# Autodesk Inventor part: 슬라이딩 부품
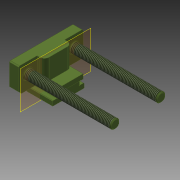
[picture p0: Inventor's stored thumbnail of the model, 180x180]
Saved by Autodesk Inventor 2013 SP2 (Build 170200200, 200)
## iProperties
Created: 2017-04
Part Number: 슬라이딩 부품
Material: 강철, 연강
Document SubType Name: Modeling
Designer: mduedu
Density: 1 g/cm^3
Author: mduedu
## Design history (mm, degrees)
sketch "스케치1"
  geometry: L1 (37, 35)-(10, 35); L2 (0, 17)-(0, 0); L3 (0, 17)-(5, 17); L4 (5, 17)-(5, 12); L5 (5, 12)-(10, 12); L6 (10, 12)-(10, 35); L7 (37, 35)-(37, 0); L8 (37, 0)-(0, 0); L9 (37, -35)-(10, -35); L10 (0, -17)-(0, 0); L11 (0, -17)-(5, -17); L12 (5, -17)-(5, -12); L13 (5, -12)-(10, -12); L14 (10, -12)-(10, -35); L15 (37, -35)-(37, 0)
  constraints: 30 end point, 6 symmetric about line, 3 perpendicular, 2 horizontal, 2 point on line, 2 vertical
  dimensions: "d39" = 5 distance of L2.start L3.end; "d41" = 70 distance between parallel lines of L9 L1; "d42" = 27 distance of L9.start L9.end; "d43" = 24 distance between parallel lines of L13 L5; "d44" = 5 distance of L4.end L5.end; "d45" = 34 distance between parallel lines of L11 L3
extrude "돌출1" new body sketch "스케치1" distance "d5" = 10; taper "d6" = 0 deg
sketch "스케치2"
  geometry: L1 (-35, 10)-(-35, 37) reference; L2 (17, 0)-(-17, 0) reference; L3 (-17, 0)-(-17, 5) reference; L4 (-17, 5)-(-12, 5) reference; L5 (-12, 5)-(-12, 10) reference; L6 (-12, 10)-(-35, 10) reference; L7 (-35, 37)-(35, 37) reference; L8 (35, 37)-(35, 10) reference; L9 (35, 10)-(12, 10) reference; L10 (12, 10)-(12, 5) reference; L11 (12, 5)-(17, 5) reference; L12 (17, 5)-(17, 0) reference; L13 (-12, 10)-(-15, 10); L14 (-15, 10)-(-15, 15); L15 (-15, 15)-(15, 15); L16 (15, 15)-(15, 10); L17 (15, 10)-(12, 10)
  constraints: 10 end point, 4 perpendicular, 2 point on line
  dimensions: "d46" = 3 distance between parallel lines of L14 L5; "d47" = 3 distance between parallel lines of L16 L10 (= d46); "d48" = 5 distance of L13.end L14.end
extrude "돌출2" join sketch "스케치2" distance "d12" = 20; taper "d13" = 0 deg
sketch "스케치3"
  geometry: L1 (0, 20)-(8, 20); L2 (8, 20)-(8, 50); L3 (8, 50)-(0, 50); L4 (0, 50)-(0, 20); L5 (0, 50)-(20, 50) reference; L6 (0, 20)-(20, 20) reference; L7 (0, 0)-(0, 70) reference; 2 further points
  constraints: 8 end point, 2 midpoint, 2 parallel, 1 horizontal, 1 perpendicular, 1 point on line
  dimensions: "d14" = 8 distance between parallel lines of L2 L4
extrude "돌출3" join sketch "스케치3" stored distance "d16" = 20; taper "d17" = 0 deg
fillet "모깎기1" dims "d18" = 5
sketch "스케치4"
  geometry: L1 (-15, 10)-(-35, 10) reference; L2 (-35, 10)-(-35, 37) reference; C1 r 5 at (-25, 25); 1 further point
  constraints: 1 centre point
  dimensions: "d19" = 10 diameter of C1; "d23" = 25 horizontal distance of point (0, 0) C1.centre (derived); "d49" = 15 distance from line of C1.centre L1; "d50" = 10 distance from line of C1.centre L2
extrude "돌출4" join sketch "스케치4" distance "d24" = 95; taper "d25" = 0 deg
feature "스레드1" dims "d26" = 10, "d27" = 0
chamfer "모따기1" distance "d28" = 1; stored, may be unused: second distance "d29" = 2, angle "d30" = 45 deg
fillet "모깎기2" dims "d31" = 1
sketch "스케치5"
  geometry: L1 (-12, 5)-(-12, 10) reference; L2 (12, 10)-(12, 5) reference; C1 r 0.5 at (-12, 10); C2 r 0.5 at (-12, 5); C3 r 0.5 at (12, 5); C4 r 0.5 at (12, 10); 1 further point
  constraints: 4 centre point, 4 coincident, 3 equal radius
  dimensions: "d51" = 1 diameter of C1
extrude "돌출5" cut sketch "스케치5" stored distance "d34" = 89; taper "d35" = 0 deg
chamfer "모따기2" distance "d36" = 3; stored, may be unused: second distance "d37" = 2, angle "d38" = 45 deg
chamfer "모따기3" distance "d52" = 0.5; stored, may be unused: second distance "d53" = 2, angle "d54" = 45 deg
sketch "스케치6"
  geometry: L1 (16.5, 5)-(17, 4.5) reference; L2 (16.5, 5)-(12.5, 5) reference; L3 (12, 5.5)-(12, 9.5) reference; L4 (-32, 10)-(-12.5, 10) reference; L5 (-12, 9.5)-(-12, 5.5) reference; L6 (-12.5, 5)-(-16.5, 5) reference; L7 (-17, 4.5)-(-16.5, 5) reference; L8 (-17, 4.5)-(-17, 0) reference; L9 (-17, 0)-(17, 0) reference; L10 (17, 0)-(17, 4.5) reference; L11 (11.5, 10)-(-11.5, 10); L12 (16.5, 5)-(17, 4.5) reference; L13 (16.5, 5)-(12.5, 5) reference; L14 (12, 5.5)-(12, 9.5) reference; L15 (12.5, 10)-(32, 10) reference; L16 (35, 13)-(32, 10) reference; L17 (35, 13)-(35, 36) reference; L18 (34, 37)-(-34, 37) reference; L19 (-35, 36)-(-35, 13) reference; L20 (-32, 10)-(-35, 13) reference; L21 (-32, 10)-(-12.5, 10) reference; L22 (-12, 9.5)-(-12, 5.5) reference; L23 (-12.5, 5)-(-16.5, 5) reference; L24 (-17, 4.5)-(-16.5, 5) reference; L25 (-17, 4.5)-(-17, 0) reference; L26 (-17, 0)-(17, 0) reference; L27 (17, 0)-(17, 4.5) reference; L28 (11.5, 5)-(-11.5, 5); L29 (34, 37)-(35, 36) reference; L30 (-35, 36)-(-34, 37) reference; A1 r 0.5 centre (12, 5) between (12, 5.5) and (12.5, 5) reference; A2 r 0.5 centre (12, 10) between (12.5, 10) and (12, 9.5) reference; A3 r 0.5 centre (-12, 10) between (-12, 9.5) and (-12.5, 10) reference; A4 r 0.5 centre (-12, 5) between (-12.5, 5) and (-12, 5.5) reference; A5 r 0.5 centre (12, 5) between (12, 5.5) and (12.5, 5) reference; A6 r 0.5 centre (12, 10) between (12.5, 10) and (12, 9.5) reference; A7 r 0.5 centre (-12, 10) between (-12, 9.5) and (-12.5, 10) reference; A8 r 0.5 centre (-12, 5) between (-12.5, 5) and (-12, 5.5) reference; 1 further point
  constraints: 4 end point, 4 point on circle, 2 collinear, 2 perpendicular
extrude "돌출6" cut sketch "스케치6" distance "d55" = 1; taper "d56" = 0 deg
node "작업 평면1"
sketch "스케치7"
  geometry: C1 r 4.2 at (-23, 25.5) reference; C2 r 4.2 at (23, 25.5) reference; 3 further points
  constraints: 2 coincident
hole "구멍1" sketch "스케치7" at (-23, 25.5), (23, 25.5) diameter "d57" = 3.242; stored, may be unused: countersink angle "d61" = 90 deg, drill point angle "d63" = 118 deg; dims "d58" = 6, "d59" = 4, "d60" = 2, "d62" = 8
mirror "대칭2"
mirror "대칭3"
node "솔리드2"
node "투영된 루프1"
node "투영된 루프2"
node "참조1"
node "참조2"
node "솔리드1"
